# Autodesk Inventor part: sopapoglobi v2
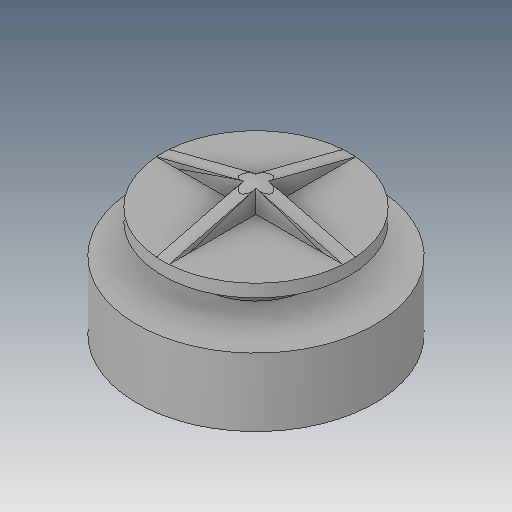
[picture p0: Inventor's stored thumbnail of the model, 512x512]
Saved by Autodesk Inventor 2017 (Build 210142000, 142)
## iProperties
Created: 2018-08
Part Number: sopapoglobi v2
Material: Plastic, Opaque Black
Document SubType Name: Modeling
Designer: JK
Density: 0.952 g/cm^3
Appearance: Smooth - Black
Sending System: Autodesk Translation Framework v7.1.0.215
Preprocessor: ST-DEVELOPER v17
Title: C:/Users/FabLab/Desktop/sopapoglobi v2.step
Author: golave@ing.uchile.cl
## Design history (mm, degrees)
feature "Body1"
sketch "Sketch1"
  geometry: C1 r 5.05 at (0, 0); 1 further point
  constraints: 1 centre point, 1 coincident
  dimensions: "d0" = 10.1 diameter of C1
extrude "Extrusion1" cut sketch "Sketch1" distance "d1" = 19; taper "d2" = 0 deg
sketch "Sketch2"
  geometry: C1 r 14 at (0, 0); C2 r 14 at (0, 0) reference; C3 r 4.95 at (0, 0); 1 further point
  constraints: 2 centre point, 2 coincident, 1 concentric
  dimensions: "d15" = 9.9 diameter of C3
extrude "Extrusion2" join sketch "Sketch2" distance "d3" = 25; taper "d4" = 0 deg
sketch "Sketch3"
  geometry: C1 r 18.001 at (0, 0); 1 further point
  constraints: 1 centre point, 1 coincident
extrude "Extrusion3" cut sketch "Sketch3" distance "d5" = 19; taper "d6" = 0 deg
sketch "Sketch4"
  geometry: C1 r 4.8 at (0, 0); 1 further point
  constraints: 1 centre point, 1 coincident
  dimensions: "d16" = 9.6 diameter of C1
extrude "Extrusion4" cut sketch "Sketch4" distance "d7" = 6.5; taper "d8" = 0 deg
sketch "Sketch5"
  geometry: C1 r 6.5 at (0, 0); 1 further point
  constraints: 1 centre point, 1 coincident
  dimensions: "d9" = 13 diameter of C1
extrude "Extrusion5" join sketch "Sketch5" stored distance "d10" = 3.25; taper "d11" = 0 deg
sketch "Sketch6"
  geometry: C1 r 11 at (0, 0); C2 r 10 at (0, 0) reference; 1 further point
  constraints: 1 centre point, 1 coincident, 1 concentric
  dimensions: "d12" = 22 diameter of C1
extrude "Extrusion6" join sketch "Sketch6" distance "d13" = 1.5; taper "d14" = 0 deg
sketch "Sketch7"
  geometry: 1 further point
sketch "Sketch8"
  geometry: L1 (0, 0)-(0, 2.628) reference; L2 (0, 2.628)-(-10.25, 0); L3 (-10.25, -1.5)-(-10.25, 0) reference; L4 (0, 2.628)-(0, 0); L5 (11.75, 0)-(-10.25, 0) reference; L6 (-10.25, 0)-(0, 0); 1 further point
  constraints: 6 end point, 2 point on line, 1 collinear, 1 vertical
extrude "Extrusion7" join sketch "Sketch8" distance "d17" = 1.5; taper "d18" = 0 deg
pattern_circular "Circular Pattern1" dims angle "d20" = 360 deg
body "Solid1"
